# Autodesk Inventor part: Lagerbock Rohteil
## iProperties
Created: 2006-02
Part Number: Lagerbock Rohteil
Document SubType Name: Modeling
Designer: Kumpf
Manufacturer: Standard
Standards Organization: Custom
Author: Kumpf
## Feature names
1. Extrusion1
2. Bohrung1 [Hole]
